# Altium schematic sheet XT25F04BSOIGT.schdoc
size 127 x 101 mm
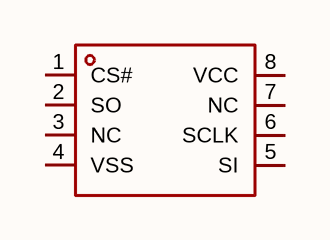
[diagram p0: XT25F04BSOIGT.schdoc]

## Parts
U?  xt25f04bsoigt  [SOP-8_L4.9-W3.9-P1.27-LS6.0-BL]  (value not drawn)

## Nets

Not connected (* = marked no-connect by the designer): U? 1(CS#) 2(SO) 3(NC) 4(VSS) 5(SI) 6(SCLK) 7(NC) 8(VCC)

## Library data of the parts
U? = xt25f04bsoigt: 接口类型:SPI;存储容量:4Mbit;时钟频率(fc):120MHz;; Manufacturer: XTX(芯天下); AddInBom: yes; ModelId: 75c24a7891ee4dd6bdac16a7163ff87e; ModelName: SOP-8_L4.9-W3.9-P1.27-LS6.0-BL-1; ModelTransform: 192.913,236.22,0,0,0,0,-0.393,2.749,0; Interface: SPI; Memory Size: 4Mbit; Clock Frequency: 120MHz; Voltage - Supply: 2.7V~3.6V; Standby Supply Current: 5uA; Program / Erase Cycles: 100000次; Page Programming Time (Tpp): 1.5ms; Block Erase Time(tBE): 800ms@(64KB); Data Retention - TDR (Year): 20年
